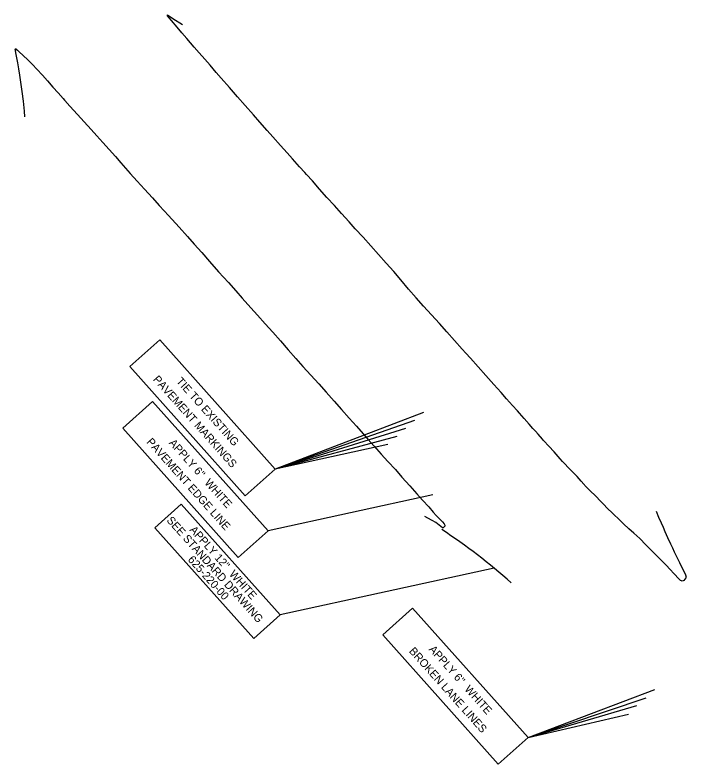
# Model space of a CAD drawing. Extents: x 1966013 to 1974896, y 789499 to 804826.
# Drawn here: x 1966690 to 1967361, y 800643 to 801392 of the extents above; entities that cross this region are included whole.
import ezdxf

# ---------------------------------------------------------------- set-up
doc = ezdxf.new("R2010")
doc.units = 0
doc.layers.add('RD_EX_H2O_BlueLn', color=7, linetype='Continuous')
doc.layers.add('RD_PD_Final_LnLine', color=7, linetype='Continuous')

msp = doc.modelspace()

# ---------------------------------------------------------------- linework, layer by layer
at = {"layer": 'RD_EX_H2O_BlueLn'}
for p, q in [((1967098.73, 800994.47), (1966950.38, 800938.01)), ((1967089.78, 800986.48), (1966950.38, 800938.01)), ((1967080.83, 800978.49), (1966950.38, 800938.01)), ((1967071.88, 800970.49), (1966950.38, 800938.01)), ((1967062.93, 800962.5), (1966950.38, 800938.01)), ((1967107.9, 800912.14), (1966943.3, 800876.17)), ((1967169.26, 800838.9), (1966955.44, 800792.17)), ((1967203.2, 800669.76), (1967329.86, 800717.52)), ((1967203.2, 800669.76), (1967321.16, 800709.35)), ((1967203.2, 800669.76), (1967312.01, 800701.59)), ((1967203.2, 800669.76), (1967303.47, 800693.11))]:
    msp.add_line(p, q, dxfattribs=at)
for points in [[(1967331.22, 800895.79), (1967333.62, 800889.95), (1967336.16, 800884.21), (1967338.14, 800879.86), (1967339.83, 800875.71), (1967342.59, 800869.49), (1967345.55, 800863.25), (1967347.51, 800859.18), (1967349.41, 800855.12), (1967351.92, 800849.93), (1967352.18, 800849.38), (1967354.57, 800844.56), (1967356.99, 800839.64), (1967360.31, 800833.22), (1967360.92, 800831.31), (1967360.89, 800831.02), (1967360.97, 800830.87), (1967361.12, 800830.05), (1967360.89, 800829.26), (1967358.93, 800826.64), (1967358.3, 800826.18), (1967357.41, 800825.96), (1967356.51, 800826.14), (1967355.76, 800826.67), (1967353.62, 800828.67), (1967349.47, 800833.06), (1967344.56, 800838.28), (1967341.8, 800841.17), (1967337.87, 800845.19), (1967332.38, 800850.9), (1967326.69, 800856.66), (1967321.1, 800862.31), (1967315.02, 800868.56), (1967308.81, 800874.03), (1967304.11, 800878.16), (1967298.74, 800883.15), (1967293.91, 800887.8), (1967288.81, 800892.76), (1967287.08, 800894.55), (1967282.96, 800898.41), (1967278.16, 800903.12), (1967276.36, 800905.13), (1967270.14, 800911.5), (1967265.66, 800915.87), (1967259.97, 800921.69), (1967259.57, 800922.21), (1967259.08, 800922.9), (1967256.43, 800925.94), (1967252.18, 800930.44), (1967246.54, 800936.22), (1967243.05, 800939.91), (1967240.42, 800942.76), (1967237.64, 800945.69), (1967235.21, 800948.23), (1967229.14, 800955.09), (1967223.92, 800960.97), (1967218.97, 800966.2), (1967218.76, 800966.51), (1967217.58, 800967.97), (1967213.33, 800972.82), (1967210.74, 800975.76), (1967208.13, 800978.72), (1967204.46, 800982.91), (1967199.21, 800988.72), (1967194.73, 800993.76), (1967192.58, 800996.19), (1967187.65, 801001.66), (1967181.8, 801008.12), (1967176.28, 801014.42), (1967168.83, 801022.64), (1967161.09, 801031.5), (1967153.39, 801040.24), (1967145.59, 801048.79), (1967141.01, 801053.93), (1967137.25, 801058.03), (1967129.66, 801066.63), (1967122.08, 801075.13), (1967114.57, 801083.58), (1967106.74, 801092.15), (1967098.83, 801100.97), (1967091.5, 801109.39), (1967083.82, 801117.97), (1967076.09, 801127.18), (1967068.88, 801135.56), (1967061.41, 801144.01), (1967053.79, 801152.5), (1967046.01, 801161.25), (1967038.32, 801169.74), (1967030.47, 801178.34), (1967024.2, 801185.37), (1967016.59, 801193.65), (1967009.57, 801201.45), (1967002.03, 801209.62), (1966994.8, 801217.98), (1966987.69, 801226.13), (1966981.72, 801232.66), (1966980.07, 801234.48), (1966974.58, 801240.2), (1966967.54, 801248.18), (1966962.24, 801254.17), (1966955.76, 801261.53), (1966948.19, 801270.24), (1966942.35, 801276.63), (1966935.03, 801284.95), (1966928.64, 801292.17), (1966920.34, 801301.59), (1966912.72, 801310.31), (1966904.77, 801319.62), (1966896.5, 801328.93), (1966891.53, 801334.6), (1966885.29, 801341.73), (1966880, 801347.73), (1966874.28, 801354.25), (1966869.46, 801359.69), (1966865.66, 801364.17), (1966861.92, 801368.6), (1966857.02, 801374.02), (1966852.26, 801379.82), (1966846.61, 801386.43), (1966842.72, 801391.34), (1966842.61, 801391.57), (1966842.55, 801391.78), (1966842.63, 801391.94), (1966842.76, 801392.03), (1966843.59, 801391.52), (1966848.16, 801388.64), (1966857.75, 801382.55)], [(1966700.14, 801290.06), (1966699.8, 801295.91), (1966698.71, 801305.74), (1966697.51, 801315.42), (1966696.57, 801322.44), (1966694.94, 801331.96), (1966693.97, 801338.3), (1966693.02, 801344.21), (1966692.05, 801349.26), (1966691.05, 801354.18), (1966690.6, 801356.37), (1966690.34, 801357.04), (1966690.24, 801357.37), (1966690.4, 801357.88), (1966690.85, 801358.16), (1966691.37, 801358.08), (1966691.5, 801357.99), (1966692.81, 801356.91), (1966694.51, 801355.29), (1966698.39, 801351.63), (1966702.96, 801347.09), (1966707.74, 801342.55), (1966712.21, 801337.76), (1966717.59, 801331.91), (1966722.84, 801326.11), (1966728.25, 801319.93), (1966733.34, 801314.24), (1966738.37, 801308.56), (1966739.88, 801306.79), (1966740.11, 801306.45), (1966745.08, 801300.77), (1966752.79, 801292.45), (1966759.25, 801285.36), (1966766.38, 801277.51), (1966772.04, 801271.23), (1966778, 801264.55), (1966784.36, 801257.6), (1966790.63, 801250.42), (1966796.17, 801244.15), (1966805.54, 801233.67), (1966812.56, 801225.84), (1966819.85, 801217.89), (1966827.62, 801209.34), (1966834.47, 801201.65), (1966839.53, 801196.34), (1966843.67, 801191.67), (1966854.36, 801179.79), (1966862.71, 801170.5), (1966869.46, 801162.84), (1966876.9, 801154.61), (1966884.86, 801145.68), (1966893.68, 801135.28), (1966903.59, 801124.64), (1966911.18, 801116.18), (1966917.49, 801108.87), (1966926.05, 801099.29), (1966932.73, 801091.91), (1966940.43, 801083.35), (1966948.1, 801074.76), (1966955.55, 801066.39), (1966963.5, 801057.37), (1966971.15, 801048.68), (1966978.19, 801040.7), (1966986.05, 801031.97), (1966994.08, 801023.27), (1967001.39, 801014.79), (1967009.3, 801005.95), (1967016.65, 800997.7), (1967024.39, 800989.01), (1967031.75, 800980.77), (1967043.03, 800967.97), (1967049.35, 800960.88), (1967056.45, 800952.95), (1967063.11, 800945.58), (1967070.56, 800937.46), (1967077.15, 800930.07), (1967084.87, 800921.32), (1967091.97, 800913.4), (1967097.76, 800907.01), (1967103.84, 800900.13), (1967108.33, 800894.95), (1967111.34, 800891.59), (1967111.96, 800891.08), (1967112.42, 800890.73), (1967113.43, 800889.69), (1967117.55, 800885.41), (1967119.28, 800883.39), (1967119.82, 800882.67), (1967120.01, 800881.8), (1967119.84, 800881.02), (1967118.81, 800879.51), (1967118.3, 800879.22), (1967118.26, 800879.22), (1967117.71, 800879.3), (1967117.59, 800879.37), (1967114.45, 800882.08), (1967111.06, 800884.48), (1967107.46, 800886.54), (1967106.61, 800886.97), (1967099.93, 800890.58)]]:
    msp.add_lwpolyline(points, dxfattribs=at)
for points in [[(1966805.09, 801040.67), (1966920.54, 800911.37), (1966950.38, 800938.01), (1966834.93, 801067.31)], [(1966798.04, 800978.8), (1966913.49, 800849.5), (1966943.33, 800876.14), (1966827.88, 801005.44)], [(1966829.99, 800879.31), (1966928.92, 800768.5), (1966955.44, 800792.17), (1966856.5, 800902.98)], [(1967057.91, 800772.42), (1967173.36, 800643.12), (1967203.2, 800669.76), (1967087.75, 800799.06)]]:
    msp.add_lwpolyline(points, close=True, dxfattribs=at)
at = {"layer": 'RD_PD_Final_LnLine'}
msp.add_arc((1966783.76, 800371.33), 606, 48.36801, 56.63992, dxfattribs=at)

# ---------------------------------------------------------------- texts
at = {"layer": 'RD_EX_H2O_BlueLn'}
for s, height, p in [('PAVEMENT MARKINGS', 8.0004, (1966827.75, 801027.3)), ('TIE TO EXISTING', 7.9995, (1966850.88, 801025.42)), ('PAVEMENT EDGE LINE', 7.9995, (1966821.29, 800964.77)), ("APPLY 6''  WHITE", 7.9996, (1966843.61, 800963.79)), ('SEE STANDARD DRAWING', 7.9995, (1966841.35, 800886.36)), ("APPLY 12''  WHITE", 7.9996, (1966864.32, 800876.89)), ('625-220-00 ', 7.9995, (1966862.53, 800847.1)), ('BROKEN LANE LINES', 8.0004, (1967083.66, 800755.59)), ("APPLY 6''  WHITE", 7.9995, (1967103.48, 800757.42))]:
    msp.add_text(s, height=height, rotation=311.76057, dxfattribs=at).set_placement(p)

doc.saveas('drawing.dxf')
